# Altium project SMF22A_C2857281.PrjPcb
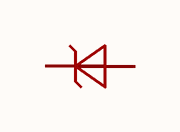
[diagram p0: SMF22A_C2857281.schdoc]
1 sheet, 1 parts. Net scope: global (net labels, ports and power ports of the same name join across sheets).

## Sheet SMF22A_C2857281.schdoc
size 127 x 101 mm

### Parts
D?  smf22a_c2857281  [SOD-123FL_L2.7-W1.8-LS3.7-RD]  (value not drawn)

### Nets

Not connected (* = marked no-connect by the designer): D? 1 2

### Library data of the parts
D? = smf22a_c2857281: 极性:单向;反向截止电压(Vrwm):22V;钳位电压:35.5V;峰值脉冲电流(Ipp):5.6A;峰值脉冲功率(Ppp):200W@10/1000us;击穿电压(VBR):24.4V;; Manufacturer: JSMSEMI(杰盛微); ManufacturerPart: SMF22A; AddInBom: yes; ModelId: 86f9151e155e4fe2af0c4f2e0a80302e; ModelName: SOD-123FL_L2.8-W1.8-H1.1-LS3.6; ModelTransform: 141.732,70.866,0,180,0,0,0,0,0; Polarity: 单向; Reverse Stand-Off Voltage (Vrwm): 22V; Clamping Voltage: 35.5V; Peak Pulse Current (Ipp): 5.6A; Voltage - Breakdown: 24.4V; Reverse Leakage Current (Ir): 1uA; Number of Channels: 单路; Type: TVS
